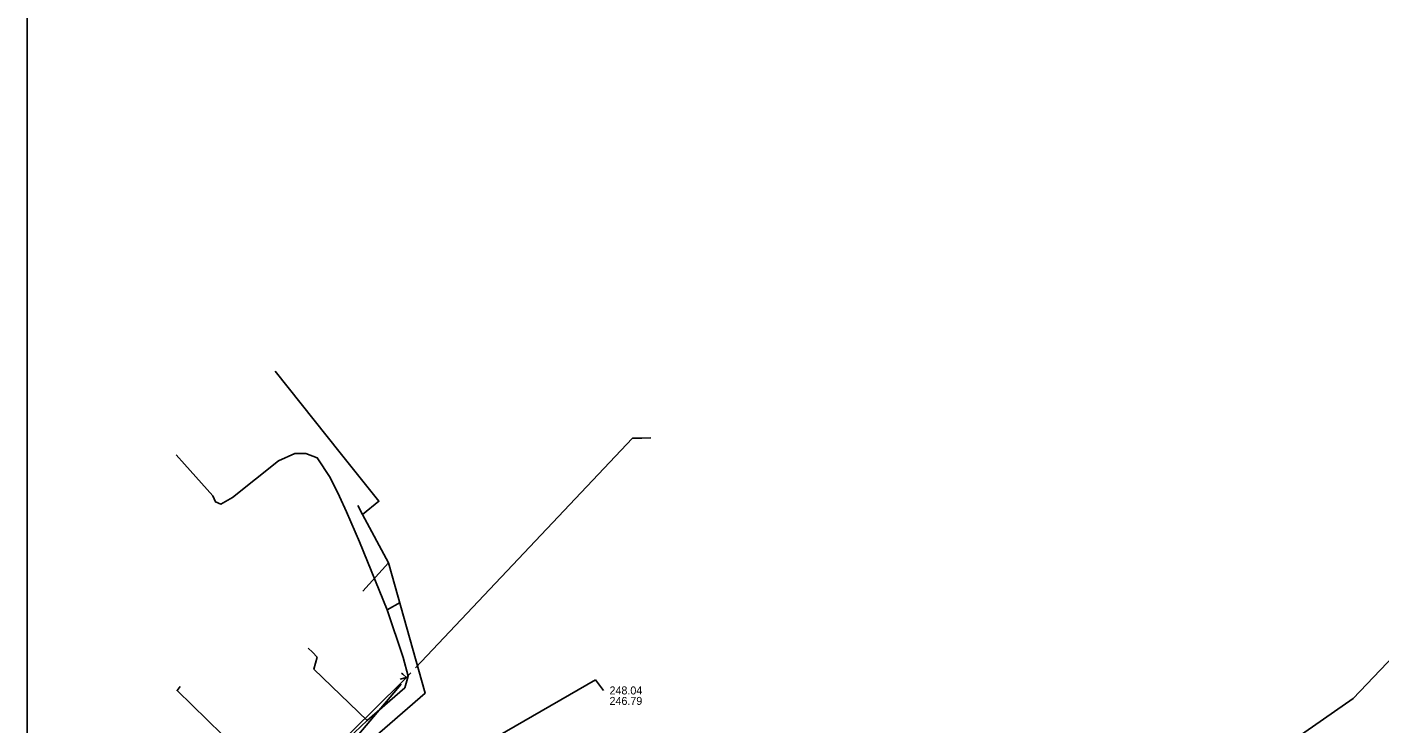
# Model space of a CAD drawing. Extents: x -598233 to -596890, y -1157848 to -1156431.
# Drawn here: x -598232.9 to -598097.6, y -1156860.8 to -1156791.1 of the extents above; entities that cross this region are included whole.
import ezdxf

# ---------------------------------------------------------------- set-up
doc = ezdxf.new("R2010")
doc.units = 0
for name, color, linetype in [('Vrstva 12', 7, 'Continuous'), ('Vrstva 16', 7, 'Continuous'), ('Vrstva 51', 7, 'Continuous'), ('Vrstva 55', 7, 'Continuous'), ('Vrstva 60', 7, 'Continuous'), ('Vrstva 9', 7, 'Continuous'), ('zajmove_uzemi', 7, 'Continuous')]:
    doc.layers.add(name, color=color, linetype=linetype)

msp = doc.modelspace()

# ---------------------------------------------------------------- linework, layer by layer
at = {"layer": 'Vrstva 12'}
for points in [[(-598100.29, -1156858.24), (-598061.49, -1156817.53), (-598059.55, -1156804.81)], [(-598196.9, -1156849.38), (-598199.66, -1156842.58), (-598200.96, -1156839.57), (-598201.65, -1156838.04), (-598202.58, -1156836.12), (-598203.88, -1156834.16), (-598205.01, -1156833.74), (-598206.11, -1156833.74), (-598207.75, -1156834.47), (-598212.36, -1156838.12), (-598213.5, -1156838.79), (-598214.04, -1156838.57), (-598214.32, -1156837.98), (-598217.14, -1156834.81), (-598217.98, -1156833.87)], [(-598196.9, -1156849.38), (-598195.57, -1156848.63)], [(-598198.87, -1156860.42), (-598195.13, -1156857.16), (-598194.8, -1156856), (-598195.3, -1156854.12), (-598196.9, -1156849.38)], [(-598198.87, -1156860.42), (-598204.23, -1156855.31), (-598203.89, -1156854.08), (-598204.35, -1156853.58), (-598204.78, -1156853.21)], [(-598206.73, -1156868.19), (-598213.37, -1156861.84), (-598217.89, -1156857.44), (-598217.59, -1156857.02)], [(-598114.8, -1156868.32), (-598100.29, -1156858.24)], [(-598203.89, -1156865.33), (-598201.4, -1156862.84), (-598198.87, -1156860.42)]]:
    msp.add_lwpolyline(points, dxfattribs=at)
at = {"layer": 'Vrstva 16'}
for points in [[(-598199.35, -1156839.82), (-598197.71, -1156838.51), (-598201.57, -1156833.66), (-598208.09, -1156825.49)], [(-598202.42, -1156865.79), (-598193.08, -1156857.7), (-598196.74, -1156844.67), (-598199.35, -1156839.82), (-598199.82, -1156838.94)], [(-598199.31, -1156847.5), (-598196.74, -1156844.67)]]:
    msp.add_lwpolyline(points, dxfattribs=at)
at = {"layer": 'Vrstva 51'}
for points in [[(-598194.04, -1156855.16), (-598172.34, -1156832.19)], [(-598172.34, -1156832.19), (-598171.41, -1156832.2), (-598170.51, -1156832.18)], [(-598194.96, -1156856.14), (-598195.41, -1156856.58), (-598223.01, -1156883.81), (-598232.89, -1156892.99)], [(-598194.96, -1156856.14), (-598195.57, -1156856.3)], [(-598194.96, -1156856.14), (-598195.33, -1156855.81), (-598195.45, -1156855.71)], [(-598194.96, -1156856.14), (-598194.52, -1156855.67)]]:
    msp.add_lwpolyline(points, dxfattribs=at)
at = {"layer": 'Vrstva 55'}
msp.add_lwpolyline([(-598195.48, -1156856.81), (-598221.49, -1156887.47), (-598232.89, -1156894.93)], dxfattribs=at)
at = {"layer": 'Vrstva 60'}
msp.add_lwpolyline([(-598232.89, -1156430.86), (-598232.89, -1157835.58)], dxfattribs=at)
at = {"layer": 'Vrstva 9'}
msp.add_line((-598175.25, -1156857.43), (-598176.07, -1156856.35), dxfattribs=at)
msp.add_lwpolyline([(-598176.07, -1156856.35), (-598192.12, -1156865.62), (-598192.99, -1156866.12)], dxfattribs=at)
at = {"layer": 'zajmove_uzemi'}
msp.add_lwpolyline([(-598232.89, -1156430.86), (-596890.46, -1156430.86), (-596890.46, -1157848.46), (-598232.89, -1157848.46)], close=True, dxfattribs=at)

# ---------------------------------------------------------------- texts
at = {"layer": 'Vrstva 12'}
for s, p in [('248.04', (-598174.65, -1156857.82)), ('246.79', (-598174.65, -1156858.87))]:
    msp.add_text(s, height=0.8, dxfattribs=at).set_placement(p)

doc.saveas('drawing.dxf')
